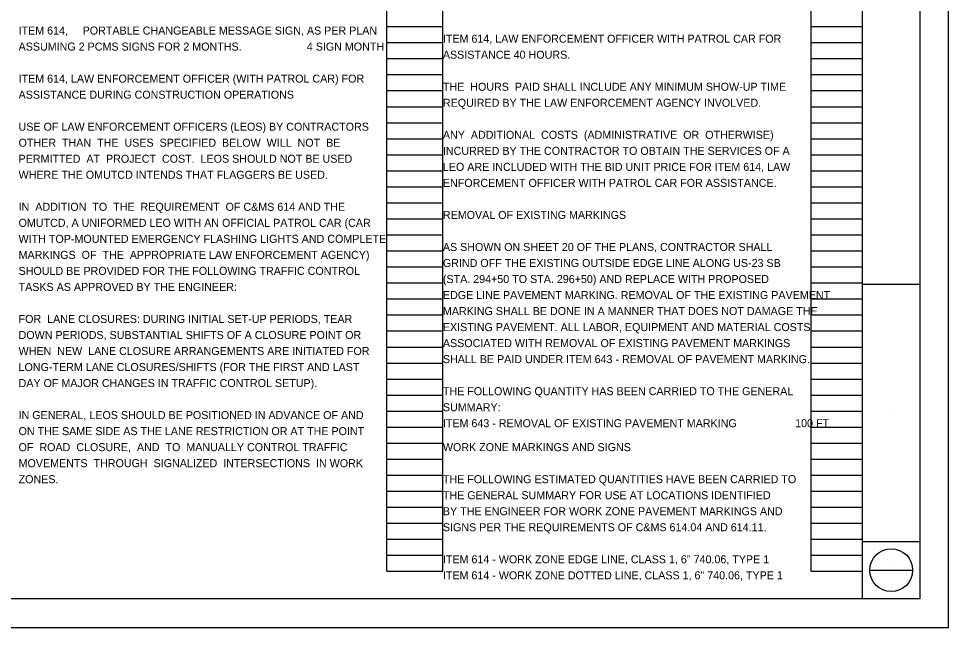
# Model space of a CAD drawing. Extents: x -51 to 34, y 0 to 22.
# Drawn here: x 17.74 to 34, y 0 to 10.64 of the extents above; entities that cross this region are included whole.
import ezdxf

# ---------------------------------------------------------------- set-up
doc = ezdxf.new("R2010")
doc.units = 0
for name, color, linetype in [('SH_Border', 7, 'Continuous'), ('SH_Cut_Line', 7, 'Continuous'), ('SH_Data', 7, 'Continuous'), ('SH_Text', 7, 'Continuous')]:
    doc.layers.add(name, color=color, linetype=linetype)

msp = doc.modelspace()

# ---------------------------------------------------------------- linework, layer by layer
at = {"layer": 'SH_Border'}
for p, q in [((32.5, 0.5), (32.5, 21.5)), ((32.5, 6), (33.5, 6)), ((32.5, 1.5), (33.5, 1.5))]:
    msp.add_line(p, q, dxfattribs=at)
msp.add_lwpolyline([(2, 21.5), (33.5, 21.5), (33.5, 0.5), (2, 0.5)], close=True, dxfattribs=at)
at = {"layer": 'SH_Cut_Line'}
msp.add_lwpolyline([(0, 0), (34, 0), (34, 22), (0, 22)], close=True, dxfattribs=at)
at = {"layer": 'SH_Data'}
for p, q in [((24.18, 0.98), (24.18, 21.14)), ((25.16, 0.98), (25.16, 21.14)), ((31.6, 0.98), (31.6, 21.14)), ((32.5, 0.98), (32.5, 21.14)), ((24.18, 10.5), (25.16, 10.5)), ((31.6, 10.5), (32.5, 10.5)), ((24.18, 10.22), (25.16, 10.22)), ((31.6, 10.22), (32.5, 10.22)), ((24.18, 9.94), (25.16, 9.94)), ((31.6, 9.94), (32.5, 9.94)), ((24.18, 9.66), (25.16, 9.66)), ((31.6, 9.66), (32.5, 9.66)), ((24.18, 9.38), (25.16, 9.38)), ((31.6, 9.38), (32.5, 9.38)), ((24.18, 9.1), (25.16, 9.1)), ((31.6, 9.1), (32.5, 9.1)), ((24.18, 8.82), (25.16, 8.82)), ((31.6, 8.82), (32.5, 8.82)), ((24.18, 8.54), (25.16, 8.54)), ((31.6, 8.54), (32.5, 8.54)), ((24.18, 8.26), (25.16, 8.26)), ((31.6, 8.26), (32.5, 8.26)), ((24.18, 7.98), (25.16, 7.98)), ((31.6, 7.98), (32.5, 7.98)), ((24.18, 7.7), (25.16, 7.7)), ((31.6, 7.7), (32.5, 7.7)), ((24.18, 7.42), (25.16, 7.42)), ((31.6, 7.42), (32.5, 7.42)), ((24.18, 7.14), (25.16, 7.14)), ((31.6, 7.14), (32.5, 7.14)), ((24.18, 6.86), (25.16, 6.86)), ((31.6, 6.86), (32.5, 6.86)), ((24.18, 6.58), (25.16, 6.58)), ((31.6, 6.58), (32.5, 6.58)), ((24.18, 6.3), (25.16, 6.3)), ((31.6, 6.3), (32.5, 6.3)), ((24.18, 6.02), (25.16, 6.02)), ((31.6, 6.02), (32.5, 6.02)), ((24.18, 5.74), (25.16, 5.74)), ((31.6, 5.74), (32.5, 5.74)), ((24.18, 5.46), (25.16, 5.46)), ((31.6, 5.46), (32.5, 5.46)), ((24.18, 5.18), (25.16, 5.18)), ((31.6, 5.18), (32.5, 5.18)), ((24.18, 4.9), (25.16, 4.9)), ((31.6, 4.9), (32.5, 4.9)), ((24.18, 4.62), (25.16, 4.62)), ((31.6, 4.62), (32.5, 4.62)), ((24.18, 4.34), (25.16, 4.34)), ((31.6, 4.34), (32.5, 4.34)), ((24.18, 4.06), (25.16, 4.06)), ((31.6, 4.06), (32.5, 4.06)), ((24.18, 3.78), (25.16, 3.78)), ((31.6, 3.78), (32.5, 3.78)), ((33, 3.792), (33, 3.792)), ((24.18, 3.5), (25.16, 3.5)), ((31.6, 3.5), (32.5, 3.5)), ((24.18, 3.22), (25.16, 3.22)), ((31.6, 3.22), (32.5, 3.22)), ((24.18, 2.94), (25.16, 2.94)), ((31.6, 2.94), (32.5, 2.94)), ((24.18, 2.66), (25.16, 2.66)), ((31.6, 2.66), (32.5, 2.66)), ((24.18, 2.38), (25.16, 2.38)), ((31.6, 2.38), (32.5, 2.38)), ((24.18, 2.1), (25.16, 2.1)), ((31.6, 2.1), (32.5, 2.1)), ((24.18, 1.82), (25.16, 1.82)), ((31.6, 1.82), (32.5, 1.82)), ((24.18, 1.54), (25.16, 1.54)), ((31.6, 1.54), (32.5, 1.54)), ((24.18, 1.26), (25.16, 1.26)), ((31.6, 1.26), (32.5, 1.26)), ((24.18, 0.98), (25.16, 0.98)), ((31.6, 0.98), (32.5, 0.98)), ((32.625, 1), (33.375, 1)), ((33, 1.085), (33, 1.085)), ((33, 0.745), (33, 0.745))]:
    msp.add_line(p, q, dxfattribs=at)
msp.add_circle((33, 1), 0.375, dxfattribs=at)

# ---------------------------------------------------------------- texts
at = {"layer": 'SH_Text'}
for s, p in [('ITEM 614,', (17.74, 10.36)), ('PORTABLE CHANGEABLE MESSAGE SIGN, AS PER PLAN', (18.86, 10.36)), ('ITEM 614, LAW ENFORCEMENT OFFICER WITH PATROL CAR FOR', (25.16, 10.218)), ('ASSUMING 2 PCMS SIGNS FOR 2 MONTHS.', (17.74, 10.08)), ('4 SIGN MONTH ', (22.78, 10.08)), ('ASSISTANCE 40 HOURS.', (25.16, 9.938)), ('ITEM 614, LAW ENFORCEMENT OFFICER (WITH PATROL CAR) FOR', (17.74, 9.52)), ('THE  HOURS  PAID SHALL INCLUDE ANY MINIMUM SHOW-UP TIME', (25.16, 9.378)), ('ASSISTANCE DURING CONSTRUCTION OPERATIONS', (17.74, 9.24)), ('REQUIRED BY THE LAW ENFORCEMENT AGENCY INVOLVED.', (25.16, 9.098)), ('USE OF LAW ENFORCEMENT OFFICERS (LEOS) BY CONTRACTORS', (17.74, 8.68)), ('ANY  ADDITIONAL  COSTS  (ADMINISTRATIVE  OR  OTHERWISE)', (25.16, 8.538)), ('OTHER  THAN  THE  USES  SPECIFIED  BELOW  WILL  NOT  BE', (17.74, 8.4)), ('INCURRED BY THE CONTRACTOR TO OBTAIN THE SERVICES OF A', (25.16, 8.258)), ('PERMITTED  AT  PROJECT  COST.  LEOS SHOULD NOT BE USED', (17.74, 8.12)), ('WHERE THE OMUTCD INTENDS THAT FLAGGERS BE USED.', (17.74, 7.84)), ('LEO ARE INCLUDED WITH THE BID UNIT PRICE FOR ITEM 614, LAW', (25.16, 7.978)), ('ENFORCEMENT OFFICER WITH PATROL CAR FOR ASSISTANCE.', (25.16, 7.698)), ('IN  ADDITION  TO  THE  REQUIREMENT  OF C&MS 614 AND THE', (17.74, 7.28)), ('REMOVAL OF EXISTING MARKINGS', (25.16, 7.138)), ('OMUTCD, A UNIFORMED LEO WITH AN OFFICIAL PATROL CAR (CAR', (17.74, 7)), ('WITH TOP-MOUNTED EMERGENCY FLASHING LIGHTS AND COMPLETE', (17.74, 6.72)), ('AS SHOWN ON SHEET 20 OF THE PLANS, CONTRACTOR SHALL', (25.16, 6.578)), ('MARKINGS  OF  THE  APPROPRIATE LAW ENFORCEMENT AGENCY)', (17.74, 6.44)), ('GRIND OFF THE EXISTING OUTSIDE EDGE LINE ALONG US-23 SB', (25.16, 6.298)), ('SHOULD BE PROVIDED FOR THE FOLLOWING TRAFFIC CONTROL', (17.74, 6.16)), ('TASKS AS APPROVED BY THE ENGINEER:', (17.74, 5.88)), ('(STA. 294+50 TO STA. 296+50) AND REPLACE WITH PROPOSED', (25.16, 6.018)), ('EDGE LINE PAVEMENT MARKING. REMOVAL OF THE EXISTING PAVEMENT', (25.16, 5.738)), ('MARKING SHALL BE DONE IN A MANNER THAT DOES NOT DAMAGE THE', (25.16, 5.458)), ('FOR  LANE CLOSURES: DURING INITIAL SET-UP PERIODS, TEAR', (17.74, 5.32)), ('EXISTING PAVEMENT. ALL LABOR, EQUIPMENT AND MATERIAL COSTS ', (25.16, 5.178)), ('DOWN PERIODS, SUBSTANTIAL SHIFTS OF A CLOSURE POINT OR', (17.74, 5.04)), ('WHEN  NEW  LANE CLOSURE ARRANGEMENTS ARE INITIATED FOR', (17.74, 4.76)), ('ASSOCIATED WITH REMOVAL OF EXISTING PAVEMENT MARKINGS', (25.16, 4.898)), ('SHALL BE PAID UNDER ITEM 643 - REMOVAL OF PAVEMENT MARKING.', (25.16, 4.618)), ('LONG-TERM LANE CLOSURES/SHIFTS (FOR THE FIRST AND LAST', (17.74, 4.48)), ('DAY OF MAJOR CHANGES IN TRAFFIC CONTROL SETUP).', (17.74, 4.2)), ('THE FOLLOWING QUANTITY HAS BEEN CARRIED TO THE GENERAL', (25.16, 4.058)), ('SUMMARY:', (25.16, 3.778)), ('IN GENERAL, LEOS SHOULD BE POSITIONED IN ADVANCE OF AND', (17.74, 3.64)), ('ITEM 643 - REMOVAL OF EXISTING PAVEMENT MARKING ', (25.16, 3.498)), ('100 FT', (31.32, 3.498)), ('ON THE SAME SIDE AS THE LANE RESTRICTION OR AT THE POINT', (17.74, 3.36)), ('OF  ROAD  CLOSURE,  AND  TO  MANUALLY CONTROL TRAFFIC', (17.74, 3.08)), ('WORK ZONE MARKINGS AND SIGNS', (25.16, 3.08)), ('MOVEMENTS  THROUGH  SIGNALIZED  INTERSECTIONS  IN WORK', (17.74, 2.8)), ('ZONES.', (17.74, 2.52)), ('THE FOLLOWING ESTIMATED QUANTITIES HAVE BEEN CARRIED TO', (25.16, 2.52)), ('THE GENERAL SUMMARY FOR USE AT LOCATIONS IDENTIFIED', (25.16, 2.24)), ('BY THE ENGINEER FOR WORK ZONE PAVEMENT MARKINGS AND', (25.16, 1.96)), ('SIGNS PER THE REQUIREMENTS OF C&MS 614.04 AND 614.11.', (25.16, 1.68)), ('ITEM 614 - WORK ZONE EDGE LINE, CLASS 1, 6" 740.06, TYPE 1', (25.16, 1.12)), ('ITEM 614 - WORK ZONE DOTTED LINE, CLASS 1, 6" 740.06, TYPE 1', (25.16, 0.84))]:
    msp.add_text(s, height=0.14, dxfattribs=at).set_placement(p)

doc.saveas('drawing.dxf')
